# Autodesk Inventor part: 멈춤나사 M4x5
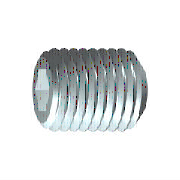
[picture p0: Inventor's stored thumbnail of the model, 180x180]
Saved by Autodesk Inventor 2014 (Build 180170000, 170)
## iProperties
IsCustomPart: 1
Created: 2012-02
Part Number: 멈춤나사 M4x5
Material: 강철, 연강
Description: 6각 소켓 머리 없는 멈춤 나사
Document SubType Name: Modeling
Standard: KS B 1028
Designer: mduedu
Standards Organization: KS
Language: ko-KR
Size Designation: 납작점M4x5
Categories: <MemberInstance><Categories><Category DisplayName="조임쇠" InternalName="e4da775c-781d-43d5-af7c-5136215cf5a6" Mnemonic="FSTN"><Category DisplayName="볼트" InternalN
Density: 1 g/cm^3
Appearance: 강철
Author: mduedu
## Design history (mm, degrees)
sketch "스케치1"
  geometry: L1 (0, 0)-(1.833, 0); L2 (5, 1.155)-(5, 2); L3 (5, 2)-(0, 2); L4 (5, 1.155)-(2.5, 1.155); L5 (2.5, 1.155)-(1.833, 0); L6 (0, -0.4)-(0, 2.4) reference; L7 (0, 2)-(0, 0)
  constraints: 13 end point, 3 parallel, 1 collinear, 1 perpendicular, 1 point on line
  dimensions: "d0" = 2.5 distance of L2.start L4.end (= INTI); "d1" = 60 deg angle of L5 L1; "d2" = 4 diameter of L3 L1 (= NND); "d3" = 2.3094 diameter of L4 L1 (= 1.1547 x SW); "d5" = 5 distance from line of L2 L3.end (= NLG)
revolve "본체" sketch "스케치1" stored, may be unused: angle "d6" = 90 deg
sketch "스케치2"
  geometry: L1 (-0.577, 1)-(0.577, 1); L2 (0.577, 1)-(1.155, 0); L3 (1.155, 0)-(0.577, -1); L4 (0.577, -1)-(-0.577, -1); L5 (-0.577, -1)-(-1.155, 0); L6 (-1.155, 0)-(-0.577, 1); A1 r 1.155 centre (0, 0) between (-0.577, 1) and (0.577, 1) reference; 2 further points
  constraints: 12 end point, 2 point on circle, 1 coincident, 1 horizontal, 11 other
extrude "슬롯" join sketch "스케치2" taper "d9" = 0 deg; stored distance "d21" = 10
workaxis "Work Axis1"
workplane "Work Plane1"
body "Solid1"
chamfer "모따기1" distance "d7" = 0.42941 (= -0.5 x GD1 + 0.5 x NND); stored, may be unused: angle "d8" = 45 deg (= FAWI), second distance "d29" = 0.42941 (= -0.5 x GD1 + 0.5 x NND)
feature "스레드" dims "d11" = 5 (= NLG), "d12" = 0
chamfer "모따기2" distance "d13" = 0.42941 (= -0.5 x GD1 + 0.5 x NND); stored, may be unused: angle "d14" = 45 deg (= FAWI), second distance "d30" = 0.42941 (= -0.5 x GD1 + 0.5 x NND)
other parameters: "NND" = 4 [user parameter; used in 5 equation terms], "NLG" = 5 [user parameter; used in 2 equation terms], "INTI" = 2.5 [user parameter; used in 1 equation term], "FAWI" = 45 deg [user parameter; used in 2 equation terms], "SW" = 2 [user parameter; used in 2 equation terms], "GD1" = 3.14117 (= THREADDIA - 1.2269 x PTC) [user parameter; used in 4 equation terms], "d4" = 0, "FAWI1" = 45 deg [user parameter], "d15" = 0, "d31" = 0, "GUL" = 0.42941 (= 0.61345 x PTC) [user parameter], "SPD" = 2.5 [user parameter], "TPU" = 14.28571 (computed from PTC) [user parameter], "TOA" = 30 deg [user parameter], "THREADDIA" = 4 [user parameter; used in 1 equation term], "PTC" = 0.7 [user parameter; used in 4 equation terms], "GAL" = 0.42941 (= 0.61345 x PTC) [user parameter], "E0" = 2.31 (= 1.155 x SW) [user parameter]
